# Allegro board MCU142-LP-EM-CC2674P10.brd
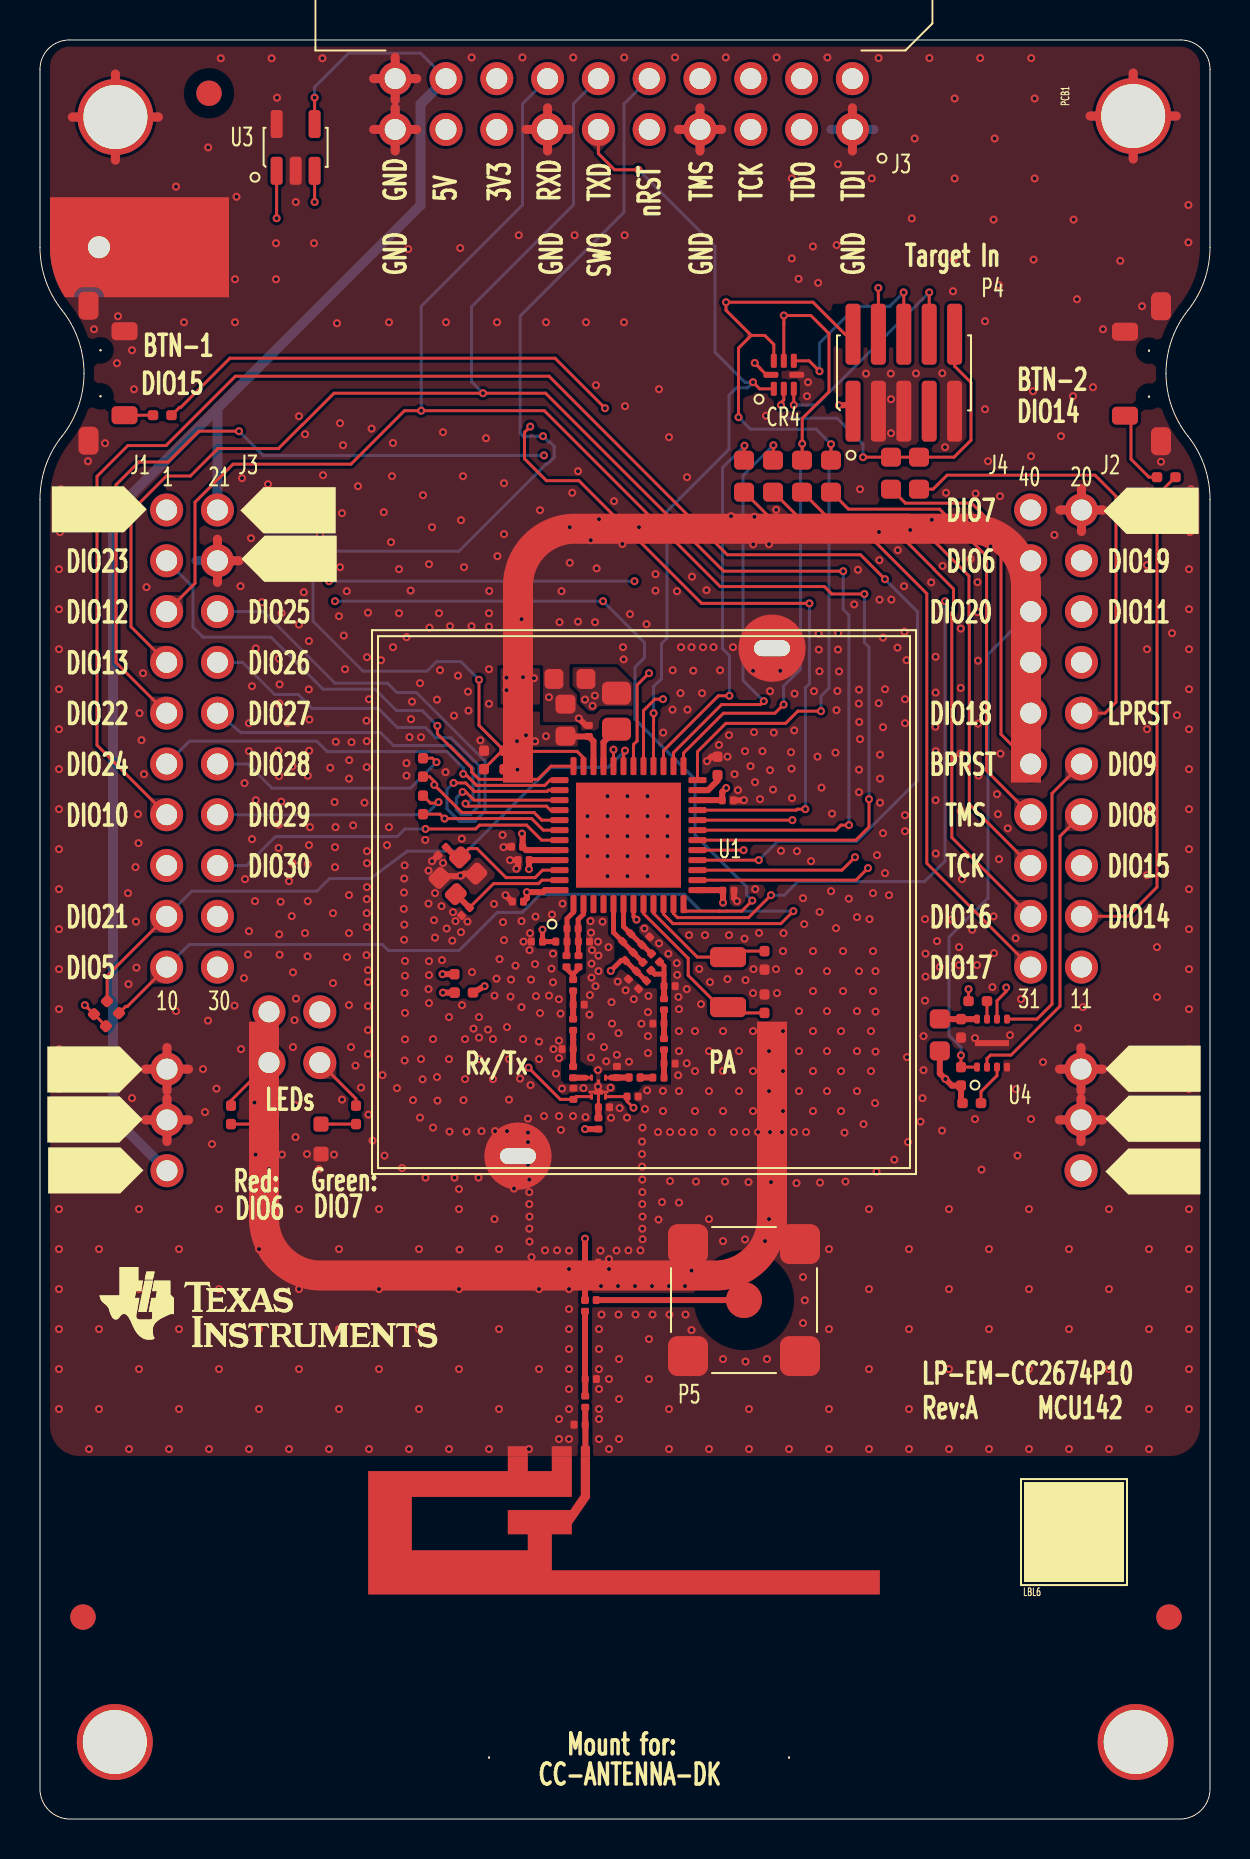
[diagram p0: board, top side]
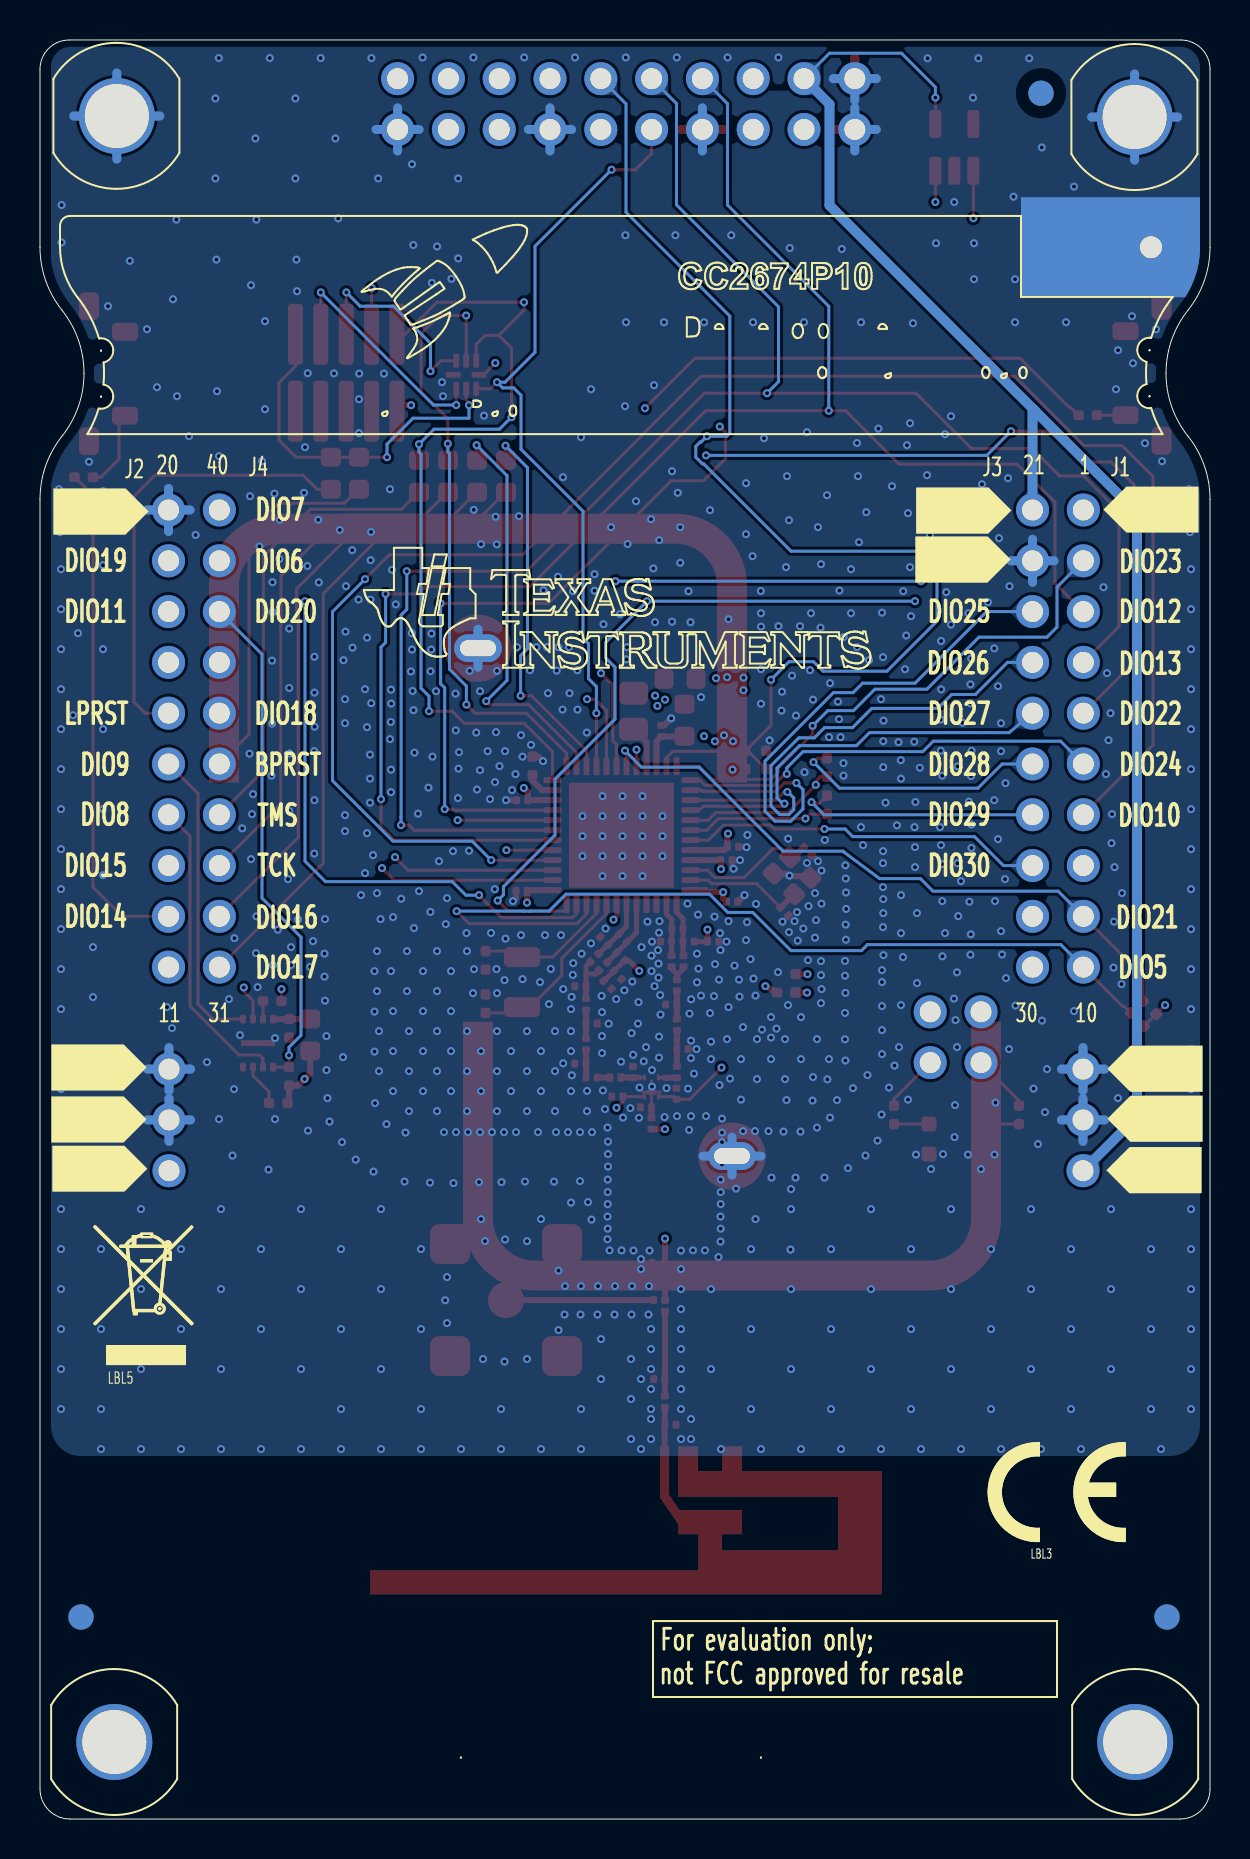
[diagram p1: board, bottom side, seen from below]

Outline 58.5 x 88.96 mm; copper layers: TOP, L2, L3, BOTTOM. Coordinates in mm from the lower left corner of the outline.
Outline path: 0,87.5 0,78.6 arc(0.28,76.93) 1.1,75.45 arc(1.92,73.97) 2.2,72.3 arc(1.92,70.63) 1.1,69.15 arc(0.28,67.67) 0,66 0,1.5 arc(0.44,0.44) 1.5,0 57,0 arc(58.06,0.44) 58.5,1.5 58.5,66 arc(58.22,67.67) 57.4,69.15 arc(56.58,70.63) 56.3,72.3 arc(56.58,73.97) 57.4,75.45 arc(58.22,76.93) 58.5,78.6 58.5,87.5 arc(58.07,88.53) 57.04,88.96 1.46,88.96 arc(0.43,88.53) 0,87.5

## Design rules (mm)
constraint set DEFAULT: min track width 0.15
nets with their own width: min track width 0.15; nets GND VDDR VDDS WMCU_VDD

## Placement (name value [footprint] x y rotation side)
A1  2.4GHz  [ANTENNA_DN007AN]  27.27 18.39 180 top
C11  12pF  [CAPC0603X35B2N]  25.12 43.88 180 top
C12  1pF  [CAPC0603X35B2N]  26.32 43.18 270 top
C13  12pF  [CAPC0603X35B2N]  26.66 37.07 90 top
C14  47pF  [CAPC0603X35B2N]  26.67 36.55 270 top
C15  12pF  [CAPC0603X35B2N]  27.81 25.95 180 top
C16  12pF  [CAPC0603X35B2N]  27.25 25.39 90 top
C21  1pF  [CAPC0603X35B2N]  27.48 43.88 180 top
C22  1pF  [CAPC0603X35B2N]  27.22 40.72 180 top
C23  1pF  [CAPC0603X35B2N]  26.1 38.5 0 top
C30  0.1uF  [CAPC1005X60B2N]  46.05 40 270 top
C31  47pF  [CAPC0603X35B2N]  29.91 36.12 180 top
C51  12pF  [CAPC0603X35B2N]  29.42 42 45 top
C52  10nF  [CAPC0603X35B2N]  30.32 41.91 225 top
C53  1.2pF  [CAPC0603X35B2N]  30.15 42.83 315 top
C56  12pF  [CAPC0603X35B2N]  31.2 37.07 180 top
C61  1.2pF  [CAPC0603X35B2N]  30.09 43.72 45 top
C62  2.7pF  [CAPC0603X35B2N]  31.2 41.65 0 top
C63  1.8pF  [CAPC0603X35B2N]  31.2 39.78 180 top
C64  2.2pF  [CAPC0603X35B2N]  31.2 37.78 0 top
C71  100nF  [CAPC0603X35B2N]  34.14 46.42 0 top
C72  100nF  [CAPC0603X35B2N]  34.11 50.94 0 top
C73  100nF  [CAPC0603X35B2N]  24.13 48.62 180 top
C74  22uF  [CAPC1608X100A2N]  26.27 54.15 90 top
C75  100nF  [CAPC0603X35B2N]  27.44 54.13 90 top
C76  22uF  [CAPC1608X100A2N]  27.29 57.01 180 top
C77  100nF  [CAPC0603X35B2N]  24.46 47.95 180 top
C78  100nF  [CAPC0603X35B2N]  24.17 45.88 180 top
C79  1uF  [CAPC1005X60B2N]  33.88 52.2 90 top
C81  12pF  [CAPC1005X60B2N]  36.22 40.31 90 top
C82  15pF  [CAPC1005X60B2N]  36.22 43.4 270 top
C83  7.5pF  [CAPC0603X35B2N]  21.47 45.57 225 top
C84  7.5pF  [CAPC0603X35B2N]  20.31 48.59 225 top
C85  0.1uF  [CAPC1005X60B2N]  22.2 52.5 90 top
CR1  TPD1E0B04DPY  [SON65P100X60X45-2A2N]  27.9 27.75 180 top
CR2  LS L296-P2Q2-1  [LEDC1708X67N]  11.45 33.25 90 top
CR3  LPL296-J2L2-25  [LEDC1707X65N]  14.05 33.25 90 top
CR4  TPD6E004RSE  [QFNFC50P150X150X60-8A2N]  36.69 71.52 0 top
FIDU1  FIDU_1.27mm  [FID127X142]  8.45 86.3 0 top
FIDU2  FIDU_1.27mm  [FID127X142]  2.15 10.1 0 top
FIDU3  FIDU_1.27mm  [FID127X142]  56.45 10.1 0 top
FIDU4  FIDU_1.27mm  [FID127X142]  8.45 86.3 180 bottom
FIDU5  FIDU_1.27mm  [FID127X142]  2.15 10.1 180 bottom
FIDU6  FIDU_1.27mm  [FID127X142]  56.45 10.1 180 bottom
FL1  BLM18HE152SN1  [FIL_BLM18HE152SN1DN]  24.15 54.9 90 top
J1  SSQ-110-23-L-D  [SAMTEC_SSQ11023LD_A2B]  6.33 65.46 0 bottom
J2  SSQ-110-23-L-D  [SAMTEC_SSQ11023LD_A2B]  49.53 65.46 0 bottom
J3  SFH11-PBPC-D10-RA-BK  [SULLINS_SFH11PBPCD10RABK_A2B]  40.62 84.49 90 top
L1  6.8uH  [INDC2012X150A2N]  28.82 54.5 90 top
L11  20nH  [INDC0603X33A2N]  26.35 44.53 0 top
L12  3.7nH  [INDC0603X33A2N]  26.35 43.88 180 top
L13  3.4nH  [INDC0603X33A2N]  26.66 41.97 270 top
L14  3.4nH  [INDC0603X33A2N]  26.66 40 270 top
L21  3.7nH  [INDC0603X33A2N]  26.92 43.18 270 top
L52  15nH  [INDC0603X33A2N]  29.14 43.87 45 top
L53  3nH  [INDC0603X33A2N]  29.26 42.94 45 top
L54  1.8nH  [INDC0603X33A2N]  31.2 41.02 270 top
L55  2.7nH  [INDC0603X33A2N]  31.2 39.03 270 top
L62  3nH  [INDC0603X33A2N]  30.58 43.26 315 top
LBL2  TI_LOGO  [TI_LOGO_1]  3.97 27.6 0 top
LBL3  CE_label  [CE_MARKING]  8.5 13.85 180 bottom
LBL4  -  [LABEL_FOR_EVALUATION_ONLY]  27.7 6.25 180 bottom
LBL5  TRASH_7mm  [TRASH_7MM]  55.2 22.7 180 bottom
LBL6  ESD_LABEL_5x5mm  [ESD_LABEL_5X5]  49.2 11.85 0 top
M1  SNT-100-BK-G  [SAMTEC_SNT100BKG]  12.7 36 90 top
M2  SNT-100-BK-G  [SAMTEC_SNT100BKG]  15.25 36 90 top
M15  DCB-12D  [MECH_DCB12D_A2B]  3.74 3.85 180 bottom
M16  DCB-12D  [MECH_DCB12D_A2B]  54.79 3.85 180 bottom
M17  DCB-12D  [MECH_DCB12D_A2B]  3.78 85.11 180 bottom
M18  DCB-12D  [MECH_DCB12D_A2B]  54.68 85.17 180 bottom
MH1  HOLE_3.2mm_PAD_3.8mm_PTH  [MTG320_380]  3.74 3.85 0 top
MH2  HOLE_3.2mm_PAD_3.8mm_PTH  [MTG320_380]  54.78 3.85 0 top
MH3  HOLE_3.2mm_PAD_3.8mm_PTH  [MTG320_380]  3.77 85.11 0 top
MH4  HOLE_3.2mm_PAD_3.8mm_PTH  [MTG320_380]  54.66 85.16 0 top
MH5  HOLE_1.1mm_PTH  [MTG110_170]  2.95 78.6 0 top
NOREF  -  []  4 27.6 0 top
NOREF#2  -  []  -1.95 35.1 0 top
NOREF#3  -  []  55.33 0 90 top
NOREF#4  -  []  8.35 62.9 0 top
NOREF#5  -  []  1.5 -22.93 0 top
NOREF#6  -  []  0.44 88.57 0 top
NOREF#7  #VALUE  [unnamed#2]  22.45 3.07 0 top
NOREF#8  -  []  -2.05 29.9 0 top
NOREF#9  -  []  -4.35 64.3 0 top
NOREF#10  -  []  -1.96 87.18 0 top
NOREF#11  -  []  -1.95 32.6 0 top
NOREF#12  -  []  8.35 60.6 0 top
NOREF#13  -  []  51.55 32.6 0 top
NOREF#14  -  []  0 87.04 0 top
NOREF#15  -  []  0.23 72.46 0 top
NOREF#16  -  []  -45.65 -55.85 0 top
NOREF#17  -  []  53.05 31 0 top
NOREF#18  -  []  0.28 116.59 0 top
NOREF#19  -  []  51.55 35.1 0 top
NOREF#20  -  []  51.45 63 0 top
NOREF#21  -  []  60.25 35.2 180 bottom
NOREF#22  -  []  60.15 63 180 bottom
NOREF#23  -  []  51.48 86.52 180 bottom
NOREF#24  -  []  17.05 60.6 180 bottom
NOREF#25  -  []  6.85 32.6 180 bottom
NOREF#26  -  []  57.95 31.3 180 bottom
NOREF#27  -  []  17.15 62.9 180 bottom
NOREF#28  -  []  5.55 64.1 180 bottom
NOREF#29  -  []  6.85 35.1 180 bottom
NOREF#30  -  []  60.25 32.6 180 bottom
NOREF#31  -  []  26.55 76.5 180 bottom
NOREF#32  -  []  6.85 29.9 180 bottom
P1  BB02-HC031-KB1-603000  [GRADCONN_BB02HC031KB1603000_A2B]  52.05 32.42 90 top
P2  BB02-HC031-KB1-603000  [GRADCONN_BB02HC031KB1603000_A2B]  6.35 32.42 90 top
P3  BB02-HJ041-KB1-603000  [GRADCONN_BB02HJ041KB1603000_A2B]  11.45 37.82 0 top
P4  FTSH-105-01-F-DV-K  [SAMTEC_FTSH10501FDVK_A2N]  40.65 70.4 0 top
P5  SMA-10V21-TGG  [HUSTSAN_SMA10V21TGGAN]  35.2 25.95 0 top
PCB1  PCB  [TI_MCUXX]  50.84 85.74 90 top
R1  100k  [RESC1005X40B2N]  23.22 53.42 270 top
R6  0  [RESC1005X40B2N]  20.72 41.32 0 top
R7  0  [RESC1005X40B2N]  20.72 41.32 90 top
R10  3.3k  [RESC1005X40B2N]  3.35 40.9 225 top
R11  2.2k  [RESC1005X40B2N]  46.05 37.6 270 top
R12  0  [RESC1608X55A2N]  44.99 40.01 270 top
R13  3.3k  [RESC1005X40B2N]  3.95 40.3 225 top
R14  180  [RESC1005X40B2N]  9.55 34.75 90 top
R15  220  [RESC1005X40B2N]  15.8 34.75 90 top
R46  DNM  [RESC1608X55A2N]  39.55 66.35 90 top
R47  DNM  [RESC1608X55A2N]  38.1 66.35 90 top
R48  0  [RESC1608X55A2N]  36.65 66.35 90 top
R49  0  [RESC1608X55A2N]  35.2 66.35 90 top
R51  0  [RESC1608X55A2N]  43.95 66.5 90 top
R52  0  [RESC1608X55A2N]  42.55 66.5 90 top
R55  100  [RESC1005X40B2N]  55.85 67.1 0 top
R56  100  [RESC1005X40B2N]  5.65 70.2 0 top
R59  DNM  [RESC1005X40B2N]  47.05 35.8 180 top
R60  DNM  [RESC1005X40B2N]  47.35 40.9 180 top
R71  DNM  [RESC1005X40B2N]  19.15 52.12 90 top
R72  DNM  [RESC1005X40B2N]  19.15 50.25 90 top
SC1  MS257-10C  [MECH_MS25710C]  30.2 45.85 0 top
SF1  MS257-10F  [MECH_MS25710F_A2N]  23.9 33.15 0 top
SW1  1188E-1K2  [SW_1188E1K2V_A2N]  2.42 75.68 270 top
SW2  1188E-1K2  [SW_1188E1K2V_A2N]  56.05 68.9 90 top
U1  CC2674P106T0RGZ  [QFNFC50P700X700X100-49A2N]  26.67 45.75 0 top
U2  RTC6608OU  [QFNFC35P100X100X40-6A2N]  28.27 37.07 180 top
U3  CAT24C08TDI  [SOT95P280X100-5A2N]  11.83 82.42 0 top
U4  MX25R8035FZUIL0  [SON50P300X200X60-9B2N]  46.85 37.6 0 top
Y1  32.768kHz  [XTAL_TZ1166C_B2N]  34.4 40.6 90 top
Y2  48MHz  [OSCCC200X160X50-4A2N]  20.79 46.25 45 top
Z60  0.9pF  [CAPC0603X35B2N]  27.82 22 180 top
Z61  3.6nH  [INDC0603X33A2N]  27.26 21.15 270 top
Z62  1.8pF  [CAPC0603X35B2N]  26.7 19.72 0 top
Z63-1  1.5nH  [INDC0603X33A2N]  30.01 37.08 180 top
Z63-2  0  [RESC0603X35B2N]  30.01 37.08 180 top
Z64  1pF  [CAPC0603X35B2N]  28.85 37.63 270 top
Z65  12pF  [CAPC0603X35B2N]  28.48 35.59 180 top
Z66  0  [RESC0603X35B2N]  27.92 34.5 90 top

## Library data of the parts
A1 = ANTENNA_DN007
C11-C16 C21-C23 C31 C51-C53 C56 C61-C64 C71-C73 C75 C77 C78 C83 C84 Z60 Z62 Z64 Z65 = CAPACITOR: User Part Number: #PN; alternate symbols: (CAPC0603X35B2L,CAPC0603X35B2M)
C30 C79 C81 C82 C85 = CAPACITOR: User Part Number: #PN
C74 C76 = CAPACITOR: User Part Number: #PN; alternate symbols: (CAPC1608X100A2L,CAPC1608X100A2M)
CR1 = DIODE_TVS_BIDIR_S: User Part Number: #PN
CR2 = LED: alternate symbols: (LEDC1708X67L,LEDC1708X67M)
CR3 = LED: alternate symbols: (LEDC1707X65L,LEDC1707X65M)
CR4 = DIODE_TVS_TPD6E004_QFN8_V1: User Part Number: #PN; alternate symbols: (QFNFC50P150X150X60-8A2L,QFNFC50P150X150X60-8A2M)
FIDU1-FIDU6 = FIDMARK
FL1 = FILTER_2PIN: alternate symbols: (FIL_BLM18HE152SN1DL,FIL_BLM18HE152SN1DM)
J1 J2 = CONN_HEADER_2X10_J_S_V1: User Part Number: #PN; alternate symbols: (SAMTEC_SSQ11023LD_A2C,SAMTEC_SSQ11023LD_A2A)
J3 = CONN_HEADER_2X10_P_V3: User Part Number: #PN; alternate symbols: (SULLINS_SFH11PBPCD10RABK_A2A,SULLINS_SFH11PBPCD10RABK_A2C)
L1 = INDUCTOR: User Part Number: #PN; alternate symbols: (INDC2012X150A2L,INDC2012X150A2M)
L11-L14 L21 L52-L55 L62 Z61 Z63-1 = INDUCTOR: User Part Number: #PN; alternate symbols: (INDC0603X33A2L,INDC0603X33A2M)
LBL2 = TI_LOGO_V1
LBL3 = CE_LABEL_V1
LBL4 = LABEL_FOR_EVALUATOIN_ONLY: User Part Number: #PN
LBL5 = TRASH_V2: User Part Number: #PN
LBL6 = ESD_LABEL: User Part Number: #PN
M1 M2 = MECH_SHUNT_JUMPER_V1: User Part Number: #PN
M15-M18 = MECH_SPACERS_SUPPORT_V1: User Part Number: #PN
MH1-MH5 = HOLE_PTH
NOREF#7 = -: User Part Number: #PN
P1 P2 = CONN_HEADER_3_P_S: User Part Number: #PN; alternate symbols: (GRADCONN_BB02HC031KB1603000_A2C,GRADCONN_BB02HC031KB1603000_A2A)
P3 = CONN_HEADER_2X2_P: User Part Number: #PN; alternate symbols: (GRADCONN_BB02HJ041KB1603000_A2C,GRADCONN_BB02HJ041KB1603000_A2A)
P4 = CONN_HEADER_2X5: User Part Number: #PN; alternate symbols: (SAMTEC_FTSH10501FDVK_A2L,SAMTEC_FTSH10501FDVK_A2M,SAMTEC_FTSH10501FDVK_B2M,SAMTEC_FTSH10501FDVK_B2L)
P5 = CONN_COAX_1_4: alternate symbols: (HUSTSAN_SMA10V21TGGL,HUSTSAN_SMA10V21TGGM)
PCB1 = PCB_V2: User Part Number: #PN
R1 R6 R7 R10 R11 R13-R15 R55 R56 R59 R60 R71 R72 = RESISTOR: User Part Number: #PN
R12 R46-R49 R51 R52 = RESISTOR: User Part Number: #PN; alternate symbols: (RESC1608X55A2L,RESC1608X55A2M)
SC1 = SHIELD_COVER: User Part Number: #PN
SF1 = SHIELD_COVER_2: User Part Number: #PN
SW1 SW2 = SWITCH_TACT_V2: alternate symbols: (SW_1188E1K2V_A2L,SW_1188E1K2V_A2M)
U1 = IC_PROC_CC2674P10_VQFN48: User Part Number: #PN; alternate symbols: (QFNFC50P700X700X100-49A2L,QFNFC50P700X700X100-49A2M)
U2 = IC_RF_RTC6608OU_QFN6: User Part Number: #PN
U3 = IC_EEPROM_CAT24C08_TSOT23-5: User Part Number: #PN; alternate symbols: (SOT95P280X100-5A2L,SOT95P280X100-5A2M)
U4 = IC_FLASH_MX25R8035F_USON8: User Part Number: #PN; alternate symbols: (SON50P300X200X60-9B2L,SON50P300X200X60-9B2M)
Y1 = XTAL: User Part Number: #PN; alternate symbols: (XTAL_TZ1166C_B2L,XTAL_TZ1166C_B2M)
Y2 = XTAL_4_V3: User Part Number: #PN; alternate symbols: (OSCCC200X160X50-4A2L,OSCCC200X160X50-4A2M)
Z63-2 Z66 = RESISTOR: User Part Number: #PN; alternate symbols: (RESC0603X35B2L,RESC0603X35B2M)

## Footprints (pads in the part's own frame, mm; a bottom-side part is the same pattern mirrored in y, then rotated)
ANTENNA_DN007AN
  rect 0.46x0.5 smd: 1(0,0)
  rect 1.001x0.5 smd: 2(1.18,0) 3(3.38,0)
CAPC0603X35B2N
  custom 0.087x0.087 smd: 1(0,0) 2(0.56,0)
CAPC1005X60B2N
  custom 0.125x0.125 smd: 1(0,0) 2(0.924,0)
CAPC1608X100A2N
  custom 0.237x0.237 smd: 1(0,0) 2(1.6,0)
FID127X142
  round 1.27 smd: 1(0,0)
FIL_BLM18HE152SN1DN
  custom 0.188x0.188 smd: 1(0,0) 2(1.4,0)
GRADCONN_BB02HC031KB1603000_A2B
  round 1.65 hole 1.05: 1(0,0) 2(2.54,0) 3(5.08,0)
GRADCONN_BB02HJ041KB1603000_A2B
  round 1.65 hole 1.05: 1(0,0) 2(0,2.54) 3(2.54,0) 4(2.54,2.54)
HUSTSAN_SMA10V21TGGAN
  round 1.8 smd: 1(0,0)
  custom 0.5x0.5 smd: 2(-2.8,-2.8) 3(2.8,-2.8) 4(2.8,2.8) 5(-2.8,2.8)
INDC0603X33A2N
  custom 0.087x0.087 smd: 1(0,0) 2(0.56,0)
INDC2012X150A2N
  custom 0.287x0.287 smd: 1(0,0) 2(1.8,0)
LEDC1707X65N
  custom 0.188x0.188 smd: 1(0,0) 2(1.501,0)
LEDC1708X67N
  custom 0.188x0.188 smd: 1(0,0) 2(1.501,0)
MECH_MS25710F_A2N
  custom 3.362x3.362 hole 1.8x0.8: 1(0,0) 2(12.7,25.4)
MTG110_170
  round 1.699 hole 1.1: 1(0,0)
MTG320_380
  round 3.8 hole 3.2: 1(0,0)
OSCCC200X160X50-4A2N
  custom 0.212x0.212 smd: 1(0,0) 2(1.45,0) 3(1.45,1.15) 4(0,1.15)
QFNFC35P100X100X40-6A2N
  custom 0.037x0.037 smd: 1(0,0) 3(0.7,0) 4(0.7,0.95) 5(0.35,0.95) 6(0,0.95)
  custom 0.189x0.189 smd: 2(0.35,0.475)
QFNFC50P150X150X60-8A2N
  custom 0.075x0.075 smd: 1(0,0) 2(0.5,0) 3(1,0) 4(1.145,0.7) 5(1,1.4) 6(0.5,1.4) 7(0,1.4) 8(-0.145,0.7)
QFNFC50P700X700X100-49A2N
  custom 0.075x0.075 smd: 1(0,0) 2(0.5,0) 3(1,0) 4(1.5,0) 5(2,0) 6(2.5,0) 7(3,0) 8(3.5,0) 9(4,0) 10(4.5,0) 11(5,0) 12(5.5,0) 13(6.2,0.7) 14(6.2,1.2) 15(6.2,1.7) 16(6.2,2.2) 17(6.2,2.7) 18(6.2,3.2) 19(6.2,3.7) 20(6.2,4.2) 21(6.2,4.7) 22(6.2,5.2) 23(6.2,5.7) 24(6.2,6.2) 25(5.5,6.9) 26(5,6.9) 27(4.5,6.9) 28(4,6.9) 29(3.5,6.9) 30(3,6.9) 31(2.5,6.9) 32(2,6.9) 33(1.5,6.9) 34(1,6.9) 35(0.5,6.9) 36(0,6.9) 37(-0.7,6.2) 38(-0.7,5.7) 39(-0.7,5.2) 40(-0.7,4.7) 41(-0.7,4.2) 42(-0.7,3.7) 43(-0.7,3.2) 44(-0.7,2.7) 45(-0.7,2.2) 46(-0.7,1.7) 47(-0.7,1.2) 48(-0.7,0.7)
  rect 5.25x5.25 smd: 49(2.75,3.45)
RESC0603X35B2N
  custom 0.087x0.087 smd: 1(0,0) 2(0.56,0)
RESC1005X40B2N
  custom 0.125x0.125 smd: 1(0,0) 2(0.924,0)
RESC1608X55A2N
  custom 0.237x0.237 smd: 1(0,0) 2(1.6,0)
SAMTEC_FTSH10501FDVK_A2N
  custom 0.188x0.188 smd: 1(0,0) 2(0,3.85) 3(1.27,0) 4(1.27,3.85) 5(2.54,0) 6(2.54,3.85) 7(3.81,0) 8(3.81,3.85) 9(5.08,0) 10(5.08,3.85)
SAMTEC_SSQ11023LD_A2B
  round 1.65 hole 1.05: 1(0,0) 2(2.54,0) 3(0,2.54) 4(2.54,2.54) 5(0,5.08) 6(2.54,5.08) 7(0,7.62) 8(2.54,7.62) 9(0,10.16) 10(2.54,10.16) 11(0,12.7) 12(2.54,12.7) 13(0,15.24) 14(2.54,15.24) 15(0,17.78) 16(2.54,17.78) 17(0,20.32) 18(2.54,20.32) 19(0,22.86) 20(2.54,22.86)
SON50P300X200X60-9B2N
  custom 0.075x0.075 smd: 1(0,0) 2(0.5,0) 3(1,0) 4(1.5,0) 5(1.5,2.4) 6(1,2.4) 7(0.5,2.4) 8(0,2.4)
  rect 1.7x0.3 smd: 9(0.75,1.2)
SON65P100X60X45-2A2N
  custom 0.075x0.075 smd: 1(0,0) 2(0.65,0)
SOT95P280X100-5A2N
  custom 0.15x0.15 smd: 1(0,0) 2(0.95,0) 3(1.9,0) 4(1.9,2.34) 5(0,2.34)
SULLINS_SFH11PBPCD10RABK_A2B
  round 1.65 hole 1.05: 1(0,0) 2(2.54,0) 3(0,2.54) 4(2.54,2.54) 5(0,5.08) 6(2.54,5.08) 7(0,7.62) 8(2.54,7.62) 9(0,10.16) 10(2.54,10.16) 11(0,12.7) 12(2.54,12.7) 13(0,15.24) 14(2.54,15.24) 15(0,17.78) 16(2.54,17.78) 17(0,20.32) 18(2.54,20.32) 19(0,22.86) 20(2.54,22.86)
SW_1188E1K2V_A2N
  round 0.099 hole 0.899 unplated: (2.229,0.6) (4.529,0.6)
  custom 0.25x0.25 smd: 1(0,0) 2(6.75,0)
  custom 0.225x0.225 smd: 3(1.275,1.8) 4(5.475,1.8)
unnamed#2
  round 0.099 hole 3.2 unplated: (0,0) (15,0)
XTAL_TZ1166C_B2N
  custom 0.25x0.25 smd: 1(0,0) 2(2.5,0)

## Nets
5V0_BP: J1.2 J3.18 P2.1 U3.4
GND: A1.2 A1.3(GND_3) C11.2 C14.1 C21.1 C22.1 C23.1 C30.2 C31.1 C51.1 C52.2 C61.2 C62.2 C63.2 C64.2 C71.2 C72.2 C73.2 C74.2 C75.2 C76.2 C77.2 C78.2 C79.2 C81.2 C82.2 C83.2 C84.2 C85.2 CR1.1 CR2.1(C) CR3.1(C) CR4.4 J1.4 J2.2 J3.1 J3.7 J3.13 J3.19 J3.20 MH3.1 MH4.1 MH5.1 P1.2 P1.3 P2.2 P2.3 P4.3 P4.5 P4.9 P5.2 P5.3 P5.4 P5.5 SF1.1 SF1.2 SW1.1 SW1.2 SW1.3 SW2.1 SW2.2 SW2.4 U1.49 U2.2 U3.2 U3.5(WP) U4.4 U4.9 Y2.2 Y2.4(GND#4) Z60.1 Z62.1 Z64.1 Z65.1
VDDR: C76.1 C77.1 C78.1 L1.2 R7.2 U1.45 U1.48
VDDS: C71.1 C72.1 C73.1 C74.1 C75.1 FL1.1 R1.2 R6.2 U1.13 U1.22 U1.34 U1.44
BP_RESET: J2.11 R52.1
DCDC_SW: L1.1 U1.33
DIO5_SDA: J1.19 R13.1 U1.10
DIO6_RLED: J2.3 P3.2 U1.11
DIO7_GLED: J2.1 P3.4 U1.12
DIO8_MISO: J2.14 U1.14 U4.2
DIO9_MOSI: J2.12 U1.15(DIO_9) U4.5
DIO10_SCLK: J1.13 U1.16 U4.6
DIO11_CS: J2.6 U1.17
DIO14_BTN2: J2.18 R55.2 U1.20
DIO15_BTN1: J2.16 R56.2 U1.21
DIO16_TDO: CR4.5 J3.4 P4.6 R48.2 U1.26
DIO17_TDI: CR4.3 J3.2 P4.8 R49.2 U1.27
DIO19_CTS: J2.4 U1.29
DIO20_FLASH_CS: J2.5 R11.1 U1.30 U4.1
DIO21_SCL: J1.17 R10.1 U1.31
DIO22: J1.9 U1.32
DIO23_ANALOG: J1.3 U1.36
DIO24_ANALOG: J1.11 U1.37
DIO25_ANALOG: J1.6 U1.38
DIO26_ANALOG: J1.8 U1.39
DIO27_ANALOG: J1.10 U1.40
DIO28_NRFPA: C31.2 R71.1 U1.41 U2.6
DIO29_NRF2G4: C14.2 R72.1 U1.42 U2.4(VC2)
DIO30_ANALOG: J1.16 U1.43
LP_RESET: J2.10 R51.1
RX_TX: C11.1 L12.2 U1.7
WMCU_RESET: C85.1 CR4.2 J3.10 P4.10 R1.1 R51.2 R52.2 U1.35
WMCU_RXD: J1.5 J3.14 U1.18
WMCU_SWO: CR4.1 J2.9 J3.11 U1.28
WMCU_TCK: CR4.6 J3.6 P4.4 R47.2 U1.25
WMCU_TMS: CR4.7 J3.8 P4.2 R46.2 U1.24
WMCU_TXD: J1.7 J3.12 U1.19
WMCU_VDD: CR4.8(VCC) FL1.2 J1.1 J3.16 P1.1 P4.1 R10.2 R11.2 R12.2 R13.2 R59.2 R60.2
XDS_BOARDID_SCL: J3.15 U3.1
XDS_BOARDID_SDA: J3.17 U3.3
N3100073: C22.2 L13.2 L14.1
N3100081: C13.2 C23.2 L14.2
N3100583: C15.2 C16.2 CR1.2 Z66.1
N3100745: C81.1 U1.8 Y1.1
N3100801: C82.1 U1.9 Y1.2
N3100989: C53.1 L52.1 L53.2 U1.5
N3100993: C16.1 Z60.2 Z61.1
N3100997: C61.1 L52.2 L62.1 U1.6
N3101171: C79.1 U1.23
N3101223: C83.1 U1.47 Y2.1
N3101429: A1.1 Z61.2 Z62.2
N3101449: C84.1 U1.46 Y2.3
N3109742: J1.12 R71.2
N3109836: J1.14 R72.2
N3109894: J2.13 R46.1
N3109960: J2.15 R47.1
N3110034: J2.17 R48.1
N3110086: J2.19 R49.1
N3110356: P3.1 R14.2
N3110380: P3.3 R15.2
N3110768: R56.1 SW1.4
N3110772: R55.1 SW2.3
N3110876: CR3.2 R15.1
N3110880: CR2.2 R14.1
N3111246: C30.1 R12.1 U4.8(VCC)
N3111262: R60.1 U4.7
N3111266: R59.1 U4.3
N3215956: C12.1 L11.1 L12.1 U1.1
N3215974: C21.2 L11.2 L21.1 U1.2
N3221205: C12.2 L13.1 L21.2
N3221963: C13.1 U2.3
N3527855: C51.2 C52.1 L53.1 R6.1 R7.1
N3527991: C53.2 C62.1 L54.1 L62.2
N3528063: C63.1 L54.2 L55.1
N3528075: C56.1 C64.1 L55.2
N3806444: C15.1 P5.1
N3819473: C56.2 Z63-1.1 Z63-2.1
N3819482: U2.1 Z63-1.2 Z63-2.2 Z64.2
N3821368: U2.5 Z65.2 Z66.2

Pads without a net: FIDU1 1; FIDU2 1; FIDU3 1; FIDU4 1; FIDU5 1; FIDU6 1; J1 15 18 20; J2 7 8 20; J3 3 5 9; MH1 1; MH2 1; P4 7; U1 3 4

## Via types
v1: diameter 0.4, hole 0.2, TOP to BOTTOM, 1095 vias

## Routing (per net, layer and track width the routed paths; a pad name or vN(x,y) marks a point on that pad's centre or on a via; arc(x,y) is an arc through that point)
5V0_BP: length 77.3
  TOP w0.15: v1(13.73,86.08) U3.4
  BOTTOM w0.15: v1(13.73,86.08) 13.73,86.61 15.42,88.3 19.03,88.3 J3.18
  BOTTOM w0.5: 8.87,70.54 19.02,80.69 19.02,85.75 J3.18 ; 8.87,70.54 J1.2 ; 8.87,70.54 3.65,65.32 3.65,35.12 P2.1
GND: length 280.8
  TOP w0.15: 1.81,78.1 MH5.1 ; MH5.1 2.07,79.48 ; MH5.1 2.95,77.5 ; MH5.1 1.85,78.6 ; MH5.1 3.45,79.74 ; MH5.1 2.45,77.46 ; MH5.1 3.45,77.46 ; MH5.1 2.45,79.74 ; MH5.1 2.07,77.72 ; MH5.1 1.81,79.1 ; MH5.1 2.95,79.7 ; MH5.1 3.83,79.48 ; MH5.1 4.09,79.1 ; MH5.1 4.09,78.1 ; MH5.1 4.05,78.6 ; MH5.1 3.83,77.72
  TOP w0.3: 19.98,47.06 20.06,47.15 21.09,47.15 21.21,47.28 21.81,47.28 ; v1(23.27,46.2) 23.6,45.88 C78.2 ; v1(23.82,47.52) 23.9,47.6 23.9,47.94 ; C84.2 19.89,48.19 v1(19.6,47.9) ; 28.62,39.75 v1(28.6,39.78) ; C77.2 v1(23.5,47.95) ; v1(34.85,45.9) 34.7,46.05 C71.2 ; C79.2 33.57,53.12 v1(33.35,52.9) ; C73.2 23.19,48.62 v1(23.17,48.6) ; C75.2 27.29,54.69 v1(26.94,55.04) ; C72.2 35.17,50.94
  TOP w0.45: 16.68,84.49 J3.19 ; J3.19 17.76,83.41 ; J3.19 18.84,84.49 ; J3.19 17.76,85.57 ; 54.66,83.01 MH4.1 ; MH4.1 54.66,87.31 ; MH4.1 56.81,85.16 ; MH4.1 52.51,85.16 ; 3.77,82.96 MH3.1 ; MH3.1 5.92,85.11 ; MH3.1 1.62,85.11 ; MH3.1 3.77,87.26 ; 33,83.41 J3.7 ; J3.7 31.92,84.49 ; J3.7 34.08,84.49 ; J3.7 33,85.57 ; P2.3 7.43,37.5 ; P2.3 5.27,37.5 ; P2.3 6.35,38.58 ; P2.3 6.35,36.42 ; P1.3 52.05,38.58 ; P1.3 53.13,37.5 ; P1.3 52.05,36.42 ; P1.3 50.97,37.5 ; 52.07,64.38 J2.2 ; J2.2 52.07,66.54 ; J2.2 51,65.46 ; J2.2 53.15,65.46 ; 5.27,34.96 P2.2 ; P2.2 7.43,34.96 ; P2.2 6.35,36.04 ; P2.2 6.35,33.88 ; J3.20 18.84,87.03 ; J3.20 16.68,87.03 ; J3.20 17.76,85.95 ; J3.20 17.76,88.11 ; J3.13 26.46,84.49 ; J3.13 24.3,84.49 ; J3.13 25.38,83.41 ; J3.13 25.38,85.57 ; J1.4 8.87,64 ; J1.4 8.87,61.84 ; J1.4 9.95,62.92 ; 50.97,34.96 P1.2 ; P1.2 52.05,36.04 ; P1.2 52.05,33.88 ; P1.2 53.13,34.96 ; 40.62,85.57 J3.1 40.62,83.41
  L2 w0.15: MH4.1 54.66,87.31 ; MH4.1 52.51,85.16 ; MH4.1 56.81,85.16 ; MH4.1 54.66,83.01 ; MH5.1 2.95,79.7 ; MH5.1 1.85,78.6 ; MH5.1 4.05,78.6 ; MH5.1 2.95,77.5 ; P2.3 6.35,38.58 ; P2.3 7.43,37.5 ; P2.3 6.35,36.42 ; P2.3 5.27,37.5 ; 52.07,64.38 J2.2 ; J2.2 52.07,66.54 ; J2.2 53.15,65.46 ; J2.2 51,65.46 ; 3.77,82.96 MH3.1 ; MH3.1 5.92,85.11 ; MH3.1 3.77,87.26 ; MH3.1 1.62,85.11 ; P1.2 53.13,34.96 ; P1.2 50.97,34.96 ; P1.2 52.05,33.88 ; P1.2 52.05,36.04 ; 33,83.41 J3.7 ; J3.7 34.08,84.49 ; J3.7 33,85.57 ; J3.7 31.92,84.49 ; 23.9,32.2 SF1.1 ; SF1.1 23.9,34.1 ; SF1.1 22.45,33.15 ; 8.87,61.84 J1.4 ; J1.4 7.8,62.92 ; J1.4 8.87,64 ; J1.4 9.95,62.92 ; P1.3 52.05,38.58 ; P1.3 53.13,37.5 ; P1.3 50.97,37.5 ; P1.3 52.05,36.42 ; 39.54,84.49 J3.1 ; J3.1 40.62,85.57 ; J3.1 40.62,83.41 ; J3.1 41.7,84.49 ; 17.76,85.95 J3.20 ; J3.20 17.76,88.11 ; J3.20 16.68,87.03 ; J3.20 18.84,87.03 ; J3.19 17.76,85.57 ; J3.19 18.84,84.49 ; J3.19 16.68,84.49 ; J3.19 17.76,83.41 ; 6.35,33.88 P2.2 ; P2.2 7.43,34.96 ; P2.2 5.27,34.96 ; P2.2 6.35,36.04 ; SF1.2 38.05,58.55 ; SF1.2 35.15,58.55 ; SF1.2 36.6,59.5 ; SF1.2 36.6,57.6 ; J3.13 26.46,84.49 ; J3.13 25.38,83.41 ; J3.13 25.38,85.57 ; J3.13 24.3,84.49
  L3 w0.15: SF1.2 36.6,59.5 ; SF1.2 36.6,57.6 ; SF1.2 38.05,58.55 ; SF1.2 35.15,58.55 ; SF1.1 23.9,34.1 ; SF1.1 22.45,33.15 ; SF1.1 23.9,32.2 ; SF1.1 25.35,33.15 ; 50.97,34.96 P1.2 52.05,36.04 ; P2.3 6.35,38.58 ; P2.3 5.27,37.5 ; P2.3 7.43,37.5 ; P2.3 6.35,36.42 ; 52.05,36.42 P1.3 ; P1.3 52.05,38.58 ; P1.3 50.97,37.5 ; 6.35,33.88 P2.2 ; P2.2 5.27,34.96 ; P2.2 6.35,36.04 ; P2.2 7.43,34.96 ; J1.4 8.87,64 ; J1.4 9.95,62.92 ; J1.4 8.87,61.84 ; J2.2 52.07,66.54 ; J2.2 52.07,64.38 ; J2.2 51,65.46
  BOTTOM w0.15: MH5.1 4.09,79.1 ; MH5.1 3.45,79.74 ; MH5.1 1.81,79.1 ; MH5.1 3.83,79.48 ; MH5.1 2.95,77.5 ; MH5.1 2.95,79.7 ; MH5.1 1.85,78.6 ; MH5.1 4.05,78.6 ; MH5.1 2.07,77.72 ; MH5.1 1.81,78.1 ; MH5.1 2.07,79.48 ; MH5.1 2.45,79.74 ; MH5.1 2.45,77.46 ; MH5.1 3.83,77.72 ; MH5.1 3.45,77.46 ; MH5.1 4.09,78.1
  BOTTOM w0.45: 25.38,83.41 J3.13 25.38,85.57 ; 52.05,36.42 P1.3 ; P1.3 53.13,37.5 ; P1.3 50.97,37.5 ; P1.3 52.05,38.58 ; 40.62,83.41 J3.1 ; J3.1 40.62,85.57 ; J3.1 39.54,84.49 ; J3.1 41.7,84.49 ; SF1.1 23.9,34.1 ; SF1.1 23.9,32.2 ; SF1.1 22.45,33.15 ; SF1.1 25.35,33.15 ; 16.68,84.49 J3.19 ; J3.19 17.76,83.41 ; J3.19 17.76,85.57 ; 8.87,61.84 J1.4 ; J1.4 8.87,64 ; J1.4 7.8,62.92 ; J1.4 9.95,62.92 ; 6.35,33.88 P2.2 ; P2.2 5.27,34.96 ; P2.2 7.43,34.96 ; P2.2 6.35,36.04 ; 33,83.41 J3.7 ; J3.7 34.08,84.49 ; J3.7 33,85.57 ; J3.7 31.92,84.49 ; P1.2 53.13,34.96 ; P1.2 52.05,36.04 ; P1.2 50.97,34.96 ; P1.2 52.05,33.88 ; 36.6,59.5 SF1.2 36.6,57.6 ; 1.62,85.11 MH3.1 ; MH3.1 3.77,87.26 ; MH3.1 5.92,85.11 ; MH3.1 3.77,82.96 ; P2.3 7.43,37.5 ; P2.3 5.27,37.5 ; P2.3 6.35,36.42 ; P2.3 6.35,38.58 ; MH4.1 56.81,85.16 ; MH4.1 52.51,85.16 ; MH4.1 54.66,87.31 ; MH4.1 54.66,83.01 ; 51,65.46 J2.2 ; J2.2 52.07,66.54 ; J2.2 52.07,64.38 ; J2.2 53.15,65.46 ; 17.76,85.95 J3.20 ; J3.20 16.68,87.03 ; J3.20 18.84,87.03
  vias: v1(0.95,62.5) v1(0.95,60.5) v1(0.95,58.5) v1(0.95,56.5) v1(0.95,54.5) v1(0.95,52.5) v1(0.95,50.5) v1(0.95,48.5) v1(0.95,46.5) v1(0.95,44.5) v1(0.95,42.5) v1(0.95,40.5) v1(0.95,38.5) v1(0.95,36.5) v1(0.95,34.5) v1(0.95,32.5) v1(0.95,30.5) v1(0.95,28.5) v1(0.95,26.5) v1(0.95,24.5) v1(0.95,22.5) v1(0.95,20.5) v1(1.05,66.5) v1(1,64.35) v1(2.4,67.9) v1(2.45,37.8) v1(2.45,18.5) v1(2.7,74.5) v1(2.95,32.5) v1(2.95,28.5) v1(2.95,24.5) v1(2.95,20.5) v1(3.25,68.8) v1(3.9,75.15) v1(3.85,72.8) v1(4.4,46.3) v1(4.42,41.75) v1(4.45,18.5) v1(4.6,73.45) v1(4.6,36.05) v1(4.7,71.5) v1(4.77,47.6) v1(4.8,44.88) v1(4.9,50.25) v1(4.82,42.57) v1(4.97,55.3) v1(4.92,48.8) v1(4.95,30.5) v1(4.95,26.5) v1(4.95,22.5) v1(5.07,53.95) v1(5.15,57.3) v1(5.2,52.25) v1(5.32,61.6) v1(6.45,18.5) v1(6.8,81.63) v1(6.8,40.4) v1(6.95,28.5) v1(6.95,24.5) v1(6.95,20.5) v1(7.2,74.85) v1(8.15,37.5) v1(8.25,35.35) v1(8.4,39.93) v1(8.41,83.59) v1(8.45,18.5) v1(8.6,33.75) v1(8.82,36.53) v1(8.95,30.5) v1(8.95,26.5) v1(8.95,22.5) v1(9.04,88.05) v1(9.75,77) v1(9.75,74.85) v1(9.72,40.68) v1(9.82,81.12) v1(10.02,61.65) v1(10.05,38.5) v1(10.1,67.05) v1(10.2,42.05) v1(10.22,51.8) v1(10.25,47) v1(10.4,43.23) v1(10.45,54.8) v1(10.45,53.4) v1(10.45,44.4) v1(10.45,18.5) v1(10.55,64.05) v1(10.6,56.65) v1(10.6,49) v1(10.79,58.54) v1(10.79,50.95) v1(10.75,45.9) v1(10.72,35.82) v1(10.77,33.22) v1(10.85,65.65) v1(10.95,28.5) v1(10.95,24.5) v1(10.95,20.5) v1(11.1,60.85) v1(11.25,62.1) v1(11.4,66.75) v1(11.45,32.5) v1(11.58,88.05) v1(11.8,78.8) v1(11.8,77) v1(11.85,86.08) v1(11.94,58.03) v1(11.98,56.74) v1(11.97,55.79) v1(11.92,53.42) v1(11.95,52.15) v1(11.93,49.73) v1(11.93,48.56) v1(11.96,44.24) v1(11.98,43.22) v1(12.08,60.3) v1(12.06,50.88) v1(12.03,45.87) v1(12.1,33.22) v1(12.37,54.82) v1(12.45,65.85) v1(12.45,46.9) v1(12.45,18.5) v1(12.59,45.15) v1(12.62,52.64) v1(12.63,47.79) v1(12.65,42.34) v1(12.65,38.6) v1(12.79,80.86) v1(12.8,41.03) v1(12.72,39.95) v1(12.75,35.7) v1(12.77,34.1) v1(12.95,70.15) v1(12.95,59.73) v1(12.95,30.5) v1(12.95,26.5) v1(12.95,22.5) v1(13,63.25) v1(13.19,61.35) v1(13.25,69.25) v1(13.25,44.3) v1(13.39,52.17) v1(13.39,47.75) v1(13.39,45.9) v1(13.38,43.14) v1(13.35,33.25) v1(13.45,58.91) v1(13.44,56.49) v1(13.47,54.98) v1(13.46,53.42) v1(13.45,48.7) v1(13.5,49.6) v1(13.7,78.8) v1(13.95,32.5) v1(14,64.2) v1(14.12,88.05) v1(14.15,67.2) v1(14.45,18.5) v1(14.51,52.57) v1(14.65,45.3) v1(14.65,41.8) v1(14.79,53.87) v1(14.73,50.85) v1(14.77,49.6) v1(14.75,48.6) v1(14.75,47.6) v1(14.7,33.22) v1(14.85,74.8) v1(14.95,60.15) v1(14.95,28.5) v1(14.95,24.5) v1(14.95,20.5) v1(15,69.8) v1(15,62.6) v1(15.15,68.7) v1(15.1,65.3) v1(15.19,59.18) v1(15.1,35.97) v1(15.25,57.5) v1(15.34,61.4) v1(15.35,43.1) v1(15.46,52.95) v1(15.45,52.03) v1(15.45,46.2) v1(15.45,44.3) v1(15.45,40.7) v1(15.57,53.85) v1(15.55,38.6) v1(15.66,49.69) v1(15.77,37.68) v1(15.9,66.65) v1(16.05,36.57) v1(16.22,50.82) v1(16.4,60.32) v1(16.35,58.1) v1(16.32,54.93) v1(16.34,53.9) v1(16.34,52.6) v1(16.35,48.4) v1(16.35,47.8) v1(16.35,46.6) v1(16.34,46) v1(16.34,45.3) v1(16.35,44.6) v1(16.32,43.2) v1(16.4,42.45) v1(16.4,41.85) v1(16.4,40.65) v1(16.4,39.45) v1(16.4,38.25) v1(16.45,56) v1(16.42,35.22) v1(16.45,18.5) v1(16.58,69.53) v1(16.62,33.93) v1(16.95,30.5) v1(16.95,26.5) v1(16.95,22.5) v1(17.05,57.95) v1(17.19,65.35) v1(17.12,37.2) v1(17.22,33.18) v1(17.35,48.7) v1(17.45,74.85) v1(17.45,49.6) v1(17.55,63.85) v1(17.65,68.81) v1(17.6,67.15) v1(17.65,58.6) v1(17.85,36.55) v1(17.95,62.5) v1(17.95,60.3) v1(18.2,46.33) v1(18.19,45.51) v1(18.1,32.55) v1(18.23,47.69) v1(18.21,47.03) v1(18.21,44.72) v1(18.2,43.97) v1(18.25,42.91) v1(18.25,42.17) v1(18.23,41.31) v1(18.25,40.31) v1(18.25,38.99) v1(18.23,37.93) v1(18.32,59.1) v1(18.32,52.8) v1(18.32,52.18) v1(18.41,78.51) v1(18.47,54.1) v1(18.45,18.5) v1(18.53,61.43) v1(18.55,55) v1(18.6,55.88) v1(18.65,35.95) v1(18.95,28.5) v1(18.95,24.5) v1(18.95,20.5) v1(19,56.8) v1(19.05,54.1) v1(19.05,38) v1(19,35.07) v1(19.15,66.2) v1(19.13,36.99) v1(19.26,48.96) v1(19.27,32.07) v1(19.45,62.75) v1(19.47,59.57) v1(19.42,47.43) v1(19.42,45.78) v1(19.45,42.9) v1(19.45,42.2) v1(19.42,41.5) v1(19.45,40.8) v1(19.6,64.6) v1(19.65,39) v1(19.65,34.57) v1(19.75,46.3) v1(19.7,44.95) v1(19.75,44.07) v1(19.85,55.97) v1(19.85,37.1) v1(19.88,35.93) v1(19.95,60.3) v1(20,57.45) v1(20.07,45.65) v1(20.15,69.35) v1(20.15,47.81) v1(20.1,42.95) v1(20.3,74.85) v1(20.27,52.35) v1(20.33,44.53) v1(20.45,40.1) v1(20.45,38) v1(20.47,34.38) v1(20.45,18.5) v1(20.5,59.65) v1(20.65,45.35) v1(20.61,43.93) v1(20.7,55.18) v1(20.77,44.9) v1(20.72,32.07) v1(20.9,57.18) v1(20.95,31.5) v1(20.95,30.5) v1(20.97,28.47) v1(20.95,26.5) v1(20.95,22.5) v1(21.01,78.56) v1(21.05,64.95) v1(21.09,49.02) v1(21.02,47.18) v1(21.05,44.35) v1(21.15,67.15) v1(21.2,62.6) v1(21.1,40.7) v1(21.17,35.95) v1(21.25,39) v1(21.25,37) v1(21.4,56.38) v1(21.38,44.88) v1(21.32,34.38) v1(21.42,55.43) v1(21.58,88.09) v1(21.57,59.65) v1(21.6,42.35) v1(21.67,39.53) v1(21.95,40.1) v1(21.95,39.07) v1(21.95,38) v1(21.92,32.07) v1(22.02,53.94) v1(22.07,34.4) v1(22.3,69.05) v1(22.4,39.47) v1(22.46,61.41) v1(22.45,60.3) v1(22.45,59.63) v1(22.45,57.5) v1(22.45,55.77) v1(22.45,18.5) v1(22.65,39) v1(22.65,37) v1(22.7,45.76) v1(22.72,41.18) v1(22.75,34.4) v1(22.72,30) v1(22.85,74.85) v1(22.87,63.15) v1(22.82,42.03) v1(22.97,43) v1(22.95,28.5) v1(22.95,24.5) v1(22.95,20.5) v1(23.2,66.8) v1(23.2,64.25) v1(23.13,49.21) v1(23.15,44.85) v1(23.2,43.95) v1(23.35,39.6) v1(23.35,34.4) v1(23.45,38) v1(23.45,35.97) v1(23.55,41.97) v1(23.52,41.12) v1(23.77,42.68) v1(23.7,31.53) v1(23.94,79.2) v1(24.07,60) v1(24.07,44.9) v1(24.07,40.6) v1(24,37.03) v1(24.12,88.09) v1(24.17,43.88) v1(24.15,39) v1(24.4,35.03) v1(24.4,34.32) v1(24.4,33.85) v1(24.4,33.3) v1(24.4,32.72) v1(24.47,43.45) v1(24.46,31.97) v1(24.46,31.35) v1(24.46,30.75) v1(24.47,30.12) v1(24.47,29.52) v1(24.47,28.88) v1(24.45,18.5) v1(24.5,44.3) v1(24.55,41.97) v1(24.52,36.7) v1(24.57,28.1) v1(24.77,45.12) v1(24.75,42.75) v1(24.8,41.15) v1(24.95,38.88) v1(24.95,38) v1(24.95,26.5) v1(24.95,22.5) v1(25,65.45) v1(25,40.3) v1(25.2,35.15) v1(25.3,74.85) v1(25.25,28.44) v1(25.45,56.1) v1(25.45,41.18) v1(25.57,42.53) v1(25.6,45.22) v1(25.65,43.28) v1(25.65,41.84) v1(25.67,38.5) v1(25.8,37.28) v1(25.85,28.44) v1(25.97,59.85) v1(25.94,40.99) v1(25.95,38.93) v1(25.95,38.05) v1(25.95,35.15) v1(25.95,20) v1(25.95,19) v1(26.07,61.4) v1(26.02,40.28) v1(26.05,34.46) v1(26.12,45.78) v1(26.1,36.53) v1(26.49,64.6) v1(26.49,62.82) v1(26.45,28.43) v1(26.45,27.5) v1(26.45,26.5) v1(26.45,25.5) v1(26.45,24.5) v1(26.45,23.5) v1(26.45,22.5) v1(26.45,21.5) v1(26.45,20.5) v1(26.45,19) v1(26.66,88.09) v1(26.61,66.32) v1(26.65,35.15) v1(26.73,79.2) v1(26.9,67.4) v1(26.9,59.88) v1(27.17,36.55) v1(27.3,74.85) v1(27.27,35.1) v1(27.38,50.15) v1(27.38,49.15) v1(27.38,48.15) v1(27.49,41.2) v1(27.47,40.22) v1(27.54,63.95) v1(27.52,44.9) v1(27.55,44.32) v1(27.57,42.78) v1(27.57,42.07) v1(27.55,39.12) v1(27.55,38.07) v1(27.6,43.45) v1(27.8,71.7) v1(27.75,59.85) v1(27.77,41.65) v1(27.83,62.54) v1(27.9,43.88) v1(27.9,37.45) v1(27.9,36.62) v1(27.95,65) v1(27.92,43.18) v1(27.92,42.4) v1(27.95,24.5) v1(27.95,23.5) v1(27.95,22.5) v1(27.95,21.5) v1(27.95,20.5) v1(27.95,20) v1(27.95,19) v1(28.02,28.43) v1(28.05,26.65) v1(28.07,25.22) v1(28.12,44.88) v1(28.2,38.6) v1(28.38,51.15) v1(28.38,50.15) v1(28.38,49.15) v1(28.38,48.15) v1(28.38,47.15) v1(28.31,37.89) v1(28.42,43.6) v1(28.45,28) v1(28.45,27.5) v1(28.45,22) v1(28.45,18.5) v1(28.57,40.85) v1(28.52,36.57) v1(28.55,35.06) v1(28.7,65.9) v1(28.89,41.88) v1(28.84,38.22) v1(28.82,28.43) v1(28.9,26.65) v1(28.92,39.3) v1(28.98,35.55) v1(28.92,25.22) v1(28.95,23) v1(28.95,21) v1(28.95,19) v1(29.2,74.85) v1(29.12,63.76) v1(29.15,58.6) v1(29.18,57.99) v1(29.21,88.09) v1(29.23,79.2) v1(29.25,70.65) v1(29.28,41.44) v1(29.38,51.15) v1(29.38,50.15) v1(29.38,49.15) v1(29.38,48.15) v1(29.38,47.15) v1(29.35,35.07) v1(29.45,37.87) v1(29.42,28.44) v1(29.5,60.25) v1(29.69,41) v1(29.75,26.65) v1(29.77,25.22) v1(29.95,64.6) v1(30.07,39.77) v1(30.02,28.44) v1(30.12,34.57) v1(30.1,33.88) v1(30.1,33.25) v1(30.1,32.62) v1(30.11,31.97) v1(30.11,31.35) v1(30.11,30.75) v1(30.12,30.12) v1(30.12,29.52) v1(30.13,28.99) v1(30.22,44.53) v1(30.25,35.5) v1(30.32,59.75) v1(30.38,51.15) v1(30.38,50.15) v1(30.38,49.15) v1(30.38,48.15) v1(30.38,47.15) v1(30.4,40.35) v1(30.4,39.15) v1(30.4,38.3) v1(30.35,36.44) v1(30.42,41.16) v1(30.45,24) v1(30.45,22) v1(30.6,26.65) v1(30.62,25.22) v1(30.77,62.25) v1(30.77,61.43) v1(30.9,34.35) v1(30.95,71.5) v1(30.95,43.79) v1(30.92,29.97) v1(31.16,54.33) v1(31.14,36.41) v1(31.15,35.4) v1(31.1,30.85) v1(31.38,50.15) v1(31.38,49.15) v1(31.38,48.15) v1(31.45,69.1) v1(31.42,43.27) v1(31.45,26.65) v1(31.47,25.22) v1(31.45,20.5) v1(31.45,18.5) v1(31.5,34.35) v1(31.5,31.9) v1(31.63,57.45) v1(31.62,55.47) v1(31.75,88.09) v1(31.85,61.4) v1(31.84,42.8) v1(31.86,42.21) v1(31.92,41.11) v1(31.95,40.5) v1(31.95,39.4) v1(31.95,38.4) v1(31.91,37.19) v1(31.95,36.4) v1(31.95,30.82) v1(32.05,58.6) v1(32.02,56.3) v1(32.1,34.35) v1(32.25,26.65) v1(32.27,25.22) v1(32.35,67.1) v1(32.38,55.47) v1(32.34,41.5) v1(32.34,37.79) v1(32.45,44.2) v1(32.58,58.6) v1(32.57,27.42) v1(32.57,24.45) v1(32.6,62.12) v1(32.66,57.43) v1(32.75,39.4) v1(32.75,37.4) v1(32.75,35.4) v1(32.7,34.35) v1(32.8,31.88) v1(32.96,42.51) v1(33.05,40.75) v1(33.15,58.6) v1(33.1,56.3) v1(33.25,44.2) v1(33.32,61.45) v1(33.45,38.4) v1(33.45,36.4) v1(33.45,30) v1(33.45,18.5) v1(33.5,41.85) v1(33.68,58.6) v1(33.6,34.35) v1(33.95,53.71) v1(34,57.45) v1(34.15,39.4) v1(34.15,37.4) v1(34.15,35.4) v1(34.15,28.9) v1(34.15,23) v1(34.29,88.09) v1(34.25,31.88) v1(34.38,53.12) v1(34.38,42) v1(34.45,54.2) v1(34.45,44.2) v1(34.55,65.15) v1(34.65,58.6) v1(34.72,52.25) v1(34.7,34.35) v1(34.9,51.45) v1(34.95,38.4) v1(34.95,36.4) v1(35.2,50.95) v1(35.25,53.4) v1(35.22,44.03) v1(35.27,41.95) v1(35.3,34.35) v1(35.25,28.98) v1(35.27,22.88) v1(35.42,31.85) v1(35.45,20.5) v1(35.45,18.5) v1(35.52,52.65) v1(35.66,63.74) v1(35.65,57.42) v1(35.67,42.5) v1(35.65,41.3) v1(35.65,39.4) v1(35.65,37.4) v1(35.65,35.4) v1(35.72,65.12) v1(35.7,54.35) v1(35.75,51.85) v1(35.76,46.5) v1(35.9,34.35) v1(35.95,44.31) v1(36,51) v1(36.12,53.4) v1(36.3,70.18) v1(36.25,28.9) v1(36.35,23) v1(36.45,63.75) v1(36.45,38.4) v1(36.45,36.4) v1(36.45,30) v1(36.5,56.4) v1(36.5,52.45) v1(36.5,34.35) v1(36.55,31.85) v1(36.69,54.33) v1(36.65,51.48) v1(36.8,42.5) v1(36.83,88.09) v1(36.81,65.47) v1(36.85,41.3) v1(37.01,57.42) v1(37.05,48.42) v1(37.17,44.3) v1(37.15,43.4) v1(37.15,39.4) v1(37.15,37.4) v1(37.15,35.4) v1(37.1,34.35) v1(37.45,18.5) v1(37.59,82.04) v1(37.59,78.04) v1(37.55,53.35) v1(37.57,52.53) v1(37.6,51.05) v1(37.72,56.28) v1(37.71,54.44) v1(37.7,34.35) v1(37.85,48.4) v1(37.82,31.8) v1(37.93,77.02) v1(37.95,42.4) v1(37.95,40.4) v1(37.95,38.4) v1(37.95,36.4) v1(38.15,46.05) v1(38.15,27.1) v1(38.15,24.8) v1(38.21,44.75) v1(38.3,34.35) v1(38.24,25.94) v1(38.4,71.85) v1(38.35,71.15) v1(38.55,47.9) v1(38.65,78.64) v1(38.65,43.4) v1(38.65,41.4) v1(38.65,39.4) v1(38.65,37.4) v1(38.65,35.4) v1(38.7,56.4) v1(38.88,53.12) v1(38.91,76.82) v1(38.93,59.28) v1(38.94,58.48) v1(38.97,57.4) v1(38.98,45.36) v1(39.07,51.57) v1(39,31.82) v1(39.37,88.09) v1(39.35,42.4) v1(39.35,40.4) v1(39.35,38.4) v1(39.35,36.4) v1(39.45,28.5) v1(39.45,24.5) v1(39.45,20.5) v1(39.45,18.5) v1(39.55,46.4) v1(39.6,50.28) v1(39.77,53.32) v1(39.8,44.55) v1(39.9,82.75) v1(39.83,78.71) v1(39.9,58.48) v1(39.87,56.41) v1(39.82,55.45) v1(39.91,59.3) v1(39.95,57.39) v1(40.05,39.4) v1(40.05,37.4) v1(40.05,35.4) v1(40.15,43.4) v1(40.15,41.4) v1(40.22,34.32) v1(40.27,31.88) v1(40.44,46.02) v1(40.71,60.74) v1(40.9,62.47) v1(40.85,45.1) v1(40.85,40.4) v1(40.85,38.4) v1(40.85,36.4) v1(40.95,56.47) v1(40.94,55.78) v1(40.96,54.86) v1(40.95,52.47) v1(40.95,51.35) v1(40.95,42.4) v1(41,66.5) v1(41,54) v1(41.17,34.75) v1(41.3,72.28) v1(41.47,45) v1(41.45,30.5) v1(41.45,26.5) v1(41.45,22.5) v1(41.45,18.5) v1(41.59,82.04) v1(41.55,39.4) v1(41.55,37.4) v1(41.65,46.3) v1(41.65,43.4) v1(41.65,41.4) v1(41.77,42.4) v1(41.77,40.38) v1(41.77,38.38) v1(41.75,35.8) v1(41.85,48.2) v1(41.82,32.38) v1(41.93,88.06) v1(41.95,64.36) v1(41.97,62.95) v1(41.97,60.97) v1(41.94,55.8) v1(42,53.22) v1(42,52.03) v1(42,50.82) v1(42.15,59.07) v1(42.15,54.6) v1(42.15,49.3) v1(42.25,56.5) v1(42.25,47.3) v1(42.45,46.2) v1(42.54,72.28) v1(42.55,71) v1(42.55,69.3) v1(42.57,60.98) v1(42.71,32.97) v1(42.89,63.45) v1(42.88,58.57) v1(43.2,61.65) v1(43.22,59.38) v1(43.25,56) v1(43.25,54.8) v1(43.25,50.2) v1(43.25,49.4) v1(43.32,57.95) v1(43.35,38.1) v1(43.4,33.85) v1(43.45,28.5) v1(43.45,24.5) v1(43.45,20.5) v1(43.45,18.5) v1(43.59,80.04) v1(43.51,64.46) v1(43.73,84.04) v1(43.8,72.29) v1(44.02,34.88) v1(44.17,39.15) v1(44.17,37.45) v1(44.12,36.05) v1(44.25,45) v1(44.27,43.28) v1(44.27,42.12) v1(44.25,40.93) v1(44.47,88.06) v1(44.59,64.97) v1(44.56,61.84) v1(44.78,58.12) v1(44.78,56.33) v1(44.77,54.62) v1(44.79,53.4) v1(44.78,50.95) v1(44.79,48.28) v1(44.85,43.9) v1(44.99,42.61) v1(45.11,72.3) v1(45.13,62.66) v1(45.1,34.43) v1(45.25,68.6) v1(45.3,66.32) v1(45.45,30.5) v1(45.45,26.5) v1(45.45,22.5) v1(45.45,18.5) v1(45.68,77.98) v1(45.65,76.4) v1(45.6,44.98) v1(45.73,86.04) v1(45.73,82.04) v1(45.95,43.6) v1(45.95,42.7) v1(46.04,59.53) v1(46.04,56.56) v1(46.02,53.28) v1(46.04,50.41) v1(46.1,47) v1(46.51,64.97) v1(46.53,63.01) v1(46.61,44.47) v1(46.78,66.28) v1(46.75,39.05) v1(46.75,35) v1(46.88,61.85) v1(46.88,60.35) v1(46.9,57.93) v1(46.9,54.78) v1(46.85,42.7) v1(46.92,52.18) v1(47.01,88.06) v1(47.07,32.47) v1(47.25,74.9) v1(47.25,70.5) v1(47.4,67.9) v1(47.45,28.5) v1(47.45,24.5) v1(47.45,18.5) v1(47.53,63.64) v1(47.68,79.98) v1(47.68,45.14) v1(47.62,41.6) v1(47.73,84.04) v1(47.7,43.3) v1(47.85,51.25) v1(47.9,50.25) v1(47.95,76.7) v1(47.95,48) v1(48,66.15) v1(48.02,53.28) v1(48.39,49.54) v1(48.5,39.2) v1(48.78,44.05) v1(48.8,36.5) v1(48.88,33.18) v1(49.05,41) v1(49.45,30.5) v1(49.45,26.5) v1(49.45,22.5) v1(49.45,18.5) v1(49.56,88.06) v1(49.55,68.15) v1(49.55,35) v1(49.68,77.98) v1(49.65,71.4) v1(49.73,86.04) v1(49.73,82.04) v1(50.15,37.85) v1(50.72,64.21) v1(51.05,69.15) v1(51.45,28.5) v1(51.45,24.5) v1(51.45,18.5) v1(51.68,79.98) v1(51.65,71.15) v1(51.85,76) v1(51.9,39.55) v1(52.15,40.6) v1(52.65,71.6) v1(53.15,74.5) v1(53.45,30.5) v1(53.45,26.5) v1(53.45,22.5) v1(53.45,18.5) v1(54.01,77.92) v1(55.1,75.65) v1(55.35,66.4) v1(55.35,62.7) v1(55.35,58.5) v1(55.35,54.5) v1(55.35,50.5) v1(55.35,47.2) v1(55.45,32.2) v1(55.45,28.5) v1(55.45,24.5) v1(55.45,20.5) v1(55.45,18.5) v1(55.85,43.6) v1(55.85,41.1) v1(55.85,36.7) v1(56.05,67.87) v1(56.6,59.3) v1(56.85,55.2) v1(57.42,80.71) v1(57.42,78.84) v1(57.45,62.5) v1(57.45,60.5) v1(57.45,58.5) v1(57.45,56.5) v1(57.45,54.5) v1(57.45,52.5) v1(57.45,50.5) v1(57.45,48.5) v1(57.45,46.5) v1(57.45,44.5) v1(57.45,42.5) v1(57.45,40.5) v1(57.45,38.5) v1(57.45,36.5) v1(57.45,34.5) v1(57.45,32.5) v1(57.45,30.5) v1(57.45,28.5) v1(57.45,26.5) v1(57.45,24.5) v1(57.45,22.5) v1(57.45,20.5) v1(57.55,66.5) v1(57.5,64.35)
VDDR: length 10.4
  TOP w0.25: v1(24.45,47.5) 24.46,47.51 C77.1
  TOP w0.3: C78.1 24.34,46.04 v1(24.34,46.35) 25.15,46.35 25.25,46.45 U1.48 ; R7.2 v1(20.12,42.25) ; U1.45 24.47,47.95 24.45,47.93 v1(24.45,47.5)
  L3 w0.3: v1(20.12,42.25) 20.71,42.84 21.2,42.84 22.08,43.72 22.08,46.28 22.07,46.29
  vias: v1(27.25,55.97) v1(27.63,55.66) v1(27.74,56.18)
VDDS: length 49.2
  TOP w0.15: v1(23.87,52.48) 23.85,52.5 R1.2
  TOP w0.3: 26.34,54.13 C75.1 27.67,53.9 U1.34 ; v1(22.23,41.65) R6.2 ; v1(24.1,49.28) 24.13,49.25 C73.1 24.3,48.45 U1.44 ; v1(34.31,51.56) 34.11,51.36 C72.1 34.1,50.95 U1.22 ; U1.13 34.11,46.45 C71.1 34.15,46.41 v1(34.15,45.82)
  L3 w0.3: v1(24.75,53.9) 25.32,53.32 25.32,46.5 24.46,45.64 23.23,45.64 22.65,45.06 22.65,43.56 22.24,43.15 22.24,42.14 22.23,42.13 v1(22.23,41.65) ; v1(34.15,45.82) 34.15,50 32.13,52.02 27.81,52.02 26.43,53.4 25.55,53.4 ; v1(25.3,54.15) 26.89,54.15 28.28,52.76 32.47,52.76 33.67,51.56 v1(34.31,51.56)
  vias: v1(23.85,53.9) v1(24.3,54.2)
BP_RESET: length 18.6
  TOP w0.15: J2.11 48.05,54.24 48.05,64.33 46.58,65.8 43.27,65.8 42.57,66.5 R52.1
DCDC_SW: length 2.1
  TOP w0.3: L1.1 28.17,53.85 U1.33
DIO5_SDA: length 44.2
  TOP w0.15: U1.10 31.17,45.25 31.65,44.78 37.04,44.78 v1(37.67,45.4) ; J1.19 4.37,40.64 4.29,40.64 R13.1
  BOTTOM w0.15: J1.19 7.46,43.72 17.13,43.72 17.43,43.43 20.95,43.43 22.86,45.34 24.11,45.34 25.02,46.25 32.2,46.25 33.05,45.4 33.97,45.4 33.97,45.4 34.33,45.4 34.33,45.4 v1(37.67,45.4)
DIO6_RLED: length 88.7
  TOP w0.15: v1(36.55,46.2) 35.42,45.07 31.88,45.07 31.67,45.28 U1.11
  L3 w0.15: J2.3 47.27,62.92 v1(45.25,60.9) 44.85,60.9 44.22,60.28 30.09,60.28 29.72,60.64 v1(29.72,61.9) ; P3.2 11.45,58.9 v1(14.45,61.9)
  BOTTOM w0.15: v1(36.55,46.2) 37.21,46.2 37.88,46.88 44.22,46.88 45.25,47.9 v1(45.25,60.9) ; v1(29.72,61.9) v1(14.45,61.9)
DIO7_GLED: length 80.4
  TOP w0.15: U1.12 32.17,45.55 32.32,45.4 33.97,45.4 33.97,45.4 34.33,45.4 34.33,45.4 35.09,45.4 v1(35.61,45.93)
  L3 w0.15: v1(28.15,60.9) 28.15,61.7 29.45,63 41.31,63 43.77,65.46 J2.1 ; P3.4 13.99,60.14 v1(14.75,60.9)
  BOTTOM w0.15: v1(35.61,45.93) 35.33,46.21 35.33,46.62 32.75,49.2 32.75,52 29.75,55 29.75,57.6 30.22,58.07 30.22,58.82 v1(28.15,60.9) v1(14.75,60.9)
DIO8_MISO: length 35.8
  TOP w0.15: U4.2 47.35,38.03 47.52,38.2 48.55,38.2 51,40.65 51,49.15 J2.14 ; v1(41.4,47.55) 40.8,46.95 U1.14
  L3 w0.15: v1(41.4,47.55) 41.8,47.55 41.94,47.69 42.41,47.69 42.54,47.55 45,47.55 46.5,49.05 50.9,49.05 J2.14
DIO9_MOSI: length 36.9
  TOP w0.15: U4.5 49.85,40 50.6,40.75 50.6,51.29 J2.12 ; U1.15 40.1,47.45 v1(40.75,48.1)
  L3 w0.15: J2.12 51.02,51.71 46.46,51.71 43.18,48.43 42.98,48.43 42.93,48.38 42.58,48.38 42.43,48.53 42.42,48.53 42.22,48.73 41.38,48.73 v1(40.75,48.1)
DIO10_SCLK: length 104.5
  TOP w0.15: v1(42.25,62) 41.03,63.22 34.37,63.22 25.45,72.15 9.77,72.15 6.3,68.68 4.39,68.68 2.85,67.14 2.85,53.7 J1.13 ; U4.6 47.85,40.92 48.31,41.38 v1(48.31,41.58) ; v1(35.94,47.95) U1.16
  L3 w0.15: v1(35.94,47.95) 37.22,47.95 40.64,44.53 45.87,44.53 48.02,42.37 48.02,41.87 v1(48.31,41.58)
  BOTTOM w0.15: v1(35.94,47.95) 36.89,48.9 40.85,48.9 42.52,50.57 43.88,51.93 43.88,60.37 v1(42.25,62)
DIO11_CS: length 27.3
  TOP w0.15: U1.17 v1(35.18,48.45)
  L3 w0.15: J2.6 50.95,59.26 50.95,54.6 50.23,53.88 41.58,53.88 40.04,52.34 38.29,52.34 35.18,49.23 v1(35.18,48.45)
DIO14_BTN2: length 47.4
  TOP w0.15: J2.18 54.39,45.14 55.85,46.6 55.85,66.19 56.76,67.1 R55.2 ; U1.20 v1(37.62,49.95)
  L3 w0.15: v1(37.62,49.95) 37.91,49.66 37.91,49.25 41.76,45.39 42.11,45.39 42.11,45.4 42.46,45.4 42.67,45.6 48.35,45.6 48.94,46.19 49.97,46.19 51.02,45.14 J2.18
DIO15_BTN1: length 79.2
  TOP w0.15: v1(28.25,70.55) 25.75,73.05 9.5,73.05 7.04,70.59 6.98,70.59 6.59,70.2 R56.2 ; v1(38.26,50.5) 37.86,50.5 37.81,50.45 U1.21 ; v1(38.47,60.79) 33.08,60.79 26.94,66.93 25.32,66.93 24.22,68.02 24.22,69.34 v1(24.51,69.63)
  L3 w0.15: v1(38.26,50.5) 38.26,49.98 40.32,47.92 41.35,46.9 42.85,46.9 43.35,46.4 48.42,46.4 48.51,46.49 50.09,46.49 50.18,46.4 50.79,46.4 J2.16 ; v1(28.25,70.55) 26.55,70.55 25.63,69.63 v1(24.51,69.63)
  BOTTOM w0.15: v1(38.26,50.5) 38.26,56.57 38.47,56.77 v1(38.47,60.79)
DIO16_TDO: length 48.6
  TOP w0.15: U1.26 31.67,53.32 34.08,55.73 36.02,55.73 v1(36.19,55.9) ; v1(36.67,68.7) 36.67,67.97 R48.2 ; P4.6 43.19,76.33 v1(43.18,76.34) ; v1(38.97,72.4) 38.45,72.92 CR4.5
  L3 w0.15: v1(36.67,68.7) 37.17,69.2 37.17,69.2 38.97,71 v1(38.97,72.4) ; J3.4 39.38,85.74 39.38,80.15 v1(43.18,76.34)
  BOTTOM w0.15: v1(36.19,55.9) 35.15,56.94 35.15,67.18 v1(36.67,68.7) ; v1(38.97,72.4) 38.97,73.8 40.82,75.65 42.5,75.65 42.5,75.66 v1(43.18,76.34)
DIO17_TDI: length 48.4
  TOP w0.15: R49.2 35.2,68.65 v1(35.22,68.68) ; U1.27 31.17,53.43 33.92,56.17 v1(34.47,56.17) ; CR4.3 v1(37.69,70.71) ; P4.8 v1(44.46,76.34)
  L3 w0.15: v1(35.22,68.68) 36.11,69.56 36.95,69.56 37.06,69.67 37.06,70.08 v1(37.69,70.71) ; J3.2 43.2,87.03 44.46,85.77 v1(44.46,76.34)
  BOTTOM w0.15: v1(37.69,70.71) 38.83,70.71 v1(44.46,76.34) ; v1(34.47,56.17) 34.47,58.18 34.12,58.52 34.12,67.57 v1(35.22,68.68)
DIO19_CTS: length 30.7
  TOP w0.15: U1.29 30.17,55.43 30.75,56 v1(31.15,56)
  L3 w0.15: v1(31.15,56) 30.75,56 29.95,56.8 29.95,57.6 31.07,58.72 31.07,58.78 31.32,59.03 31.38,59.03 32.27,59.93 45.67,59.93 47.37,61.62 50.77,61.62 J2.4
DIO20_FLASH_CS: length 51.1
  TOP w0.15: v1(46.05,38.19) R11.1 U4.1 ; U1.30 29.67,53.73 29.86,53.91 29.86,56.71 v1(30.45,57.3)
  L3 w0.15: v1(30.45,57.3) 30.85,57.3 31.19,56.96 45.08,56.96 48.5,60.38 J2.5
  BOTTOM w0.15: J2.5 47.4,58.25 47.4,46.05 45.45,44.1 45.45,39.19 46.05,38.59 v1(46.05,38.19)
DIO21_SCL: length 32.5
  TOP w0.15: R10.1 3.36,40.91 3.36,42.16 J1.17 ; U1.31 29.17,53.35 v1(29.25,53.43)
  BOTTOM w0.15: v1(29.25,53.43) 28.42,52.6 25.55,52.6 21.35,48.4 21.34,48.4 18.35,48.4 18.3,48.35 16.51,47.03 14.47,47.03 13.85,46.4 7.59,46.4 J1.17
DIO22: length 52.5
  TOP w0.15: U1.32 v1(28.67,53.47) ; v1(9.95,69.4) 7.95,69.4 6.41,67.86 4.94,67.86 3.8,66.72 3.8,57.83 J1.9
  L3 w0.15: v1(28.67,53.47) 28.67,53.88 28.57,53.98 28.57,57.88 28.56,57.9 28.56,59.79 25.88,62.47 25.88,67.51 25.66,67.74 25.66,67.74 v1(25.2,68.19)
  BOTTOM w0.15: v1(9.95,69.4) 11.16,68.19 v1(25.2,68.19)
DIO23_ANALOG: length 26.7
  TOP w0.15: U1.36 25.55,52.65 24.89,51.99 21.95,51.99 21.58,52.36 21.58,52.55 19.87,54.26 v1(19.87,54.67)
  BOTTOM w0.15: v1(19.87,54.67) 19.11,55.43 17.82,55.43 16.75,56.5 14.15,56.5 11.55,59.1 8.15,59.1 7.65,59.6 7.65,61.6 J1.3
DIO24_ANALOG: length 21.3
  TOP w0.15: v1(21.16,52.26) 21.26,52.26 21.83,51.69 25.24,51.69 25.5,51.95 U1.37
  BOTTOM w0.15: J1.11 7.47,53.9 13.84,53.9 14.36,53.38 20.35,53.38 21.16,52.56 v1(21.16,52.26)
DIO25_ANALOG: length 28.3
  TOP w0.15: v1(20.68,51.81) 21.28,51.81 21.7,51.39 25.36,51.39 25.42,51.45 U1.38
  BOTTOM w0.15: v1(20.68,51.81) 20.35,51.48 20.35,50.51 20.96,49.9 21.75,49.9 22.25,50.4 22.25,52.9 18.83,56.32 17.85,56.32 17.37,56.8 14.75,56.8 11.17,60.38 J1.6
DIO26_ANALOG: length 24.7
  TOP w0.15: U1.39 21.7,50.95 21.29,51.36 v1(21.13,51.36)
  BOTTOM w0.15: v1(21.13,51.36) 21.11,51.36 20.81,51.06 20.81,50.47 21.06,50.22 21.51,50.22 21.95,50.66 21.95,52.68 20.56,54.07 19.78,54.07 19.27,54.57 17.87,54.57 17.62,54.82 17.47,54.97 16.91,55.54 13.61,55.54 12.91,56.23 11.73,56.23 10.12,57.84 J1.8
DIO27_ANALOG: length 20.7
  TOP w0.15: U1.40 25.52,50.45 25.32,50.65 21.4,50.65 v1(21.27,50.78)
  BOTTOM w0.15: J1.10 10.05,54.32 17.03,54.32 17.68,53.68 20.52,53.68 21.65,52.55 21.65,51.06 21.36,50.78 v1(21.27,50.78)
DIO28_NRFPA: length 37.6
  TOP w0.15: U1.41 25.08,49.95 24.71,50.33 21.1,50.33 v1(19.71,51.71) 19.71,51.89 19.47,52.12 R71.1 ; U2.6 C31.2 29.35,35.88 v1(29.67,35.56)
  L3 w0.15: v1(19.71,51.71) 18.72,50.73 18.72,49.22 17.42,47.92 17.42,37.93 18.8,36.55 23.75,36.55 24.32,35.97 29.26,35.97 v1(29.67,35.56)
DIO29_NRF2G4: length 28.8
  TOP w0.15: R72.1 20,50.25 20.22,50.03 v1(20.23,50.03) 24.58,50.03 25.16,49.45 U1.42 ; U2.4 26.81,36.12 C14.2 26.27,35.99 26.27,35.99 26.01,35.99 v1(24.42,37.57)
  L3 w0.15: v1(24.42,37.57) 20.2,37.57 18.88,38.9 18.88,47.85 20.23,49.2 v1(20.23,50.03)
DIO30_ANALOG: length 18.3
  TOP w0.15: v1(19.27,49.51) 21.78,49.51 21.97,49.7 24.33,49.7 25.08,48.95 U1.43
  BOTTOM w0.15: v1(19.27,49.51) 18.25,49.51 17.86,49.12 11.77,49.12 10.33,47.68 J1.16
LP_RESET: length 22.8
  TOP w0.15: R51.1 44.65,66.5 45.35,67.2 52.75,67.2 53.8,66.15 53.8,55.85 53.25,55.3 J2.10
RX_TX: length 7.7
  TOP w0.2: v1(29.82,44.97) 29.67,45.12 U1.7
  TOP w0.25: v1(25.12,44.47) C11.1 L12.2
  L3 w0.3: v1(25.12,44.47) 25.6,44.47 26.95,45.82 28.97,45.82 v1(29.82,44.97)
WMCU_RESET: length 90.7
  TOP w0.15: 23.22,53.42 23.22,53.41 23.22,53.39 ; 23.22,53.42 R1.1 ; 23.22,53.42 21.95,54.69 v1(21.95,56.97) ; P4.10 45.73,72.65 46.55,71.83 46.55,68.95 45.7,68.1 R51.2 R52.2 v1(41.15,68.1) ; 23.22,53.39 26.86,53.39 27.17,53.07 U1.35 ; 23.22,53.39 23.08,53.39 22.2,52.51 C85.1 ; CR4.2 37.19,70.97 37.05,70.83 v1(37.05,70.7)
  L3 w0.15: v1(25.15,69.15) 29.9,69.15 31.45,70.7 35.2,70.7 35.44,70.47 35.76,70.47 35.99,70.7 v1(37.05,70.7)
  BOTTOM w0.15: v1(21.95,56.97) 21.05,57.88 19.82,57.88 19.35,57.4 16.15,57.4 13.65,59.9 13.65,62.4 14.65,63.4 20.95,63.4 25.31,67.76 25.38,67.76 25.71,68.1 25.71,68.64 25.48,68.87 25.44,68.87 v1(25.15,69.15) 24.16,69.15 24.01,69.3 24.01,75.16 29.2,80.35 29.2,85.77 J3.10 ; v1(37.05,70.7) 37.05,70.05 39.85,70.05 41.15,68.75 v1(41.15,68.1)
WMCU_RXD: length 85
  TOP w0.15: U1.18 40.79,48.95 41.45,49.61 v1(41.45,51) ; v1(41.22,61.26) 39.59,61.26 39.22,61.63 34.01,61.63 25.21,70.43 v1(19.06,70.43) 18.22,70.43 15.55,67.75 9.65,67.75 7.75,65.85 7.75,61.8 J1.5
  BOTTOM w0.15: v1(19.06,70.43) 19.06,75.65 24.12,80.71 24.12,85.77 J3.14 ; v1(41.22,61.26) 41.22,58.83 41.45,58.6 v1(41.45,51)
WMCU_SWO: length 58.7
  TOP w0.15: CR4.1 35.98,71.52 v1(35.65,71.85) ; v1(29.92,82.48) 28.72,82.48 27.92,83.28 J3.11 ; v1(30.68,55.3) 30.68,54.9 30.67,54.89 U1.28
  L3 w0.15: J2.9 40.66,55.3 40.23,54.88 31.1,54.88 v1(30.68,55.3)
  BOTTOM w0.15: v1(29.92,82.48) 33.75,78.65 33.75,73.35 35.25,71.85 v1(35.65,71.85) 35.36,71.56 34.81,71.56 34.45,71.2 34.45,68.5 31.35,65.4 31.35,59.05 31.07,58.78 31.07,57.03 30.68,56.63 v1(30.68,55.3)
WMCU_TCK: length 52
  TOP w0.15: v1(41.92,76.57) 41.92,76.16 41.92,76.16 P4.4 ; v1(37.18,55.73) 36.75,55.3 34.17,55.3 32.17,53.3 U1.25 ; CR4.6 37.19,74.77 37.19,74.78 v1(37.19,75.19) 38.54,75.19 39.45,74.28 39.45,71.37 38.11,70.03 v1(38.11,68.78) 38.11,67.96 R47.2
  L3 w0.15: J3.6 36.91,85.66 36.91,75.47 v1(37.19,75.19) 39.01,75.19 40.39,76.57 v1(41.92,76.57)
  BOTTOM w0.15: v1(38.11,68.78) 38.11,68.37 38.02,68.29 38.02,57.5 37.18,56.66 v1(37.18,55.73)
WMCU_TMS: length 55.4
  TOP w0.15: CR4.7 36.69,73.74 36.24,74.19 35.56,74.19 ; 35.56,74.19 34.3,75.45 v1(34.3,75.85) 38.65,75.85 40.25,74.25 P4.2 ; 35.56,74.19 34.92,73.55 v1(34.92,70.1) ; v1(39.05,55.4) 37.89,55.4 37.28,54.79 34.29,54.79 32.88,53.37 U1.24 ; v1(39.55,68.75) R46.2
  L3 w0.15: v1(34.3,75.85) 34.3,85.73 J3.8
  BOTTOM w0.15: v1(39.05,55.4) 39.05,56.15 39.45,56.55 39.45,68.25 39.55,68.35 v1(39.55,68.75) 38.8,69.5 35.52,69.5 v1(34.92,70.1)
WMCU_TXD: length 89.1
  TOP w0.15: v1(40.45,49.7) 40.05,49.7 39.8,49.45 U1.19 ; v1(40.16,62.4) 34.18,62.4 25.28,71.3 v1(22.15,71.3) 14.7,71.3 13.13,69.72 13.12,69.72 11.92,68.53 8.89,68.53 7.52,67.16 6.32,67.16 4.55,65.39 4.55,59.62 J1.7
  BOTTOM w0.15: v1(22.15,71.3) 21.57,71.88 21.57,75.62 26.67,80.72 26.67,85.79 J3.12 ; v1(40.16,62.4) 40.16,60.49 40.44,60.21 40.44,50.11 40.45,50.1 v1(40.45,49.7)
WMCU_VDD: length 62
  TOP w0.15: 46.05,35.88 R59.2 ; CR4.8 36.32,72.22 36.03,72.51 36.03,72.52 v1(35.74,72.81) ; 3.3,39.65 v1(2.24,40.7) ; R60.2 v1(46.43,41.5)
  TOP w0.3: 46.05,35.88 R11.2 45.6,36.68 v1(45.27,37) 44.99,37.28 R12.2 ; FL1.2 v1(24.15,57.1) ; v1(39.95,70.7) 40.35,70.7 P4.1
  L3 w0.3: J1.1 7.6,64.19 7.6,42.15 6.15,40.7 v1(2.24,40.7) ; 50.97,32.42 48.62,32.42 45.27,35.77 45.27,37 v1(45.27,37) 45.27,37.48 45.27,37.49 45.27,40.35 v1(46.42,41.5)
  L3 w0.45: 50.97,32.42 P1.1 ; P1.1 52.05,33.5 ; P1.1 53.13,32.42 ; J3.16 23.92,87.03 ; J3.16 22.84,85.95 ; J3.16 22.84,88.11 ; J1.1 6.33,66.54 ; J1.1 5.26,65.46 ; J1.1 7.41,65.46 ; J1.1 6.33,64.38
  vias: v1(23.32,57.07) v1(23.32,56.45) v1(24.7,57.05)
